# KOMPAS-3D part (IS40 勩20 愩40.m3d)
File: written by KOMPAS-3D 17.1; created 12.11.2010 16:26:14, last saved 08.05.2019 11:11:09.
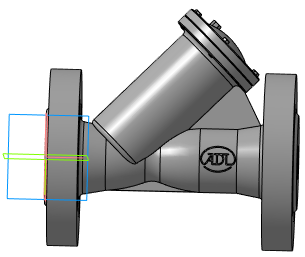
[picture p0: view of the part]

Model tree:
1. Плоскость XY
2. Плоскость ZX
3. Плоскость ZY
4. Ось X
5. Ось Y
6. Ось Z
7. Начало координат
8. Операция без истории:2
